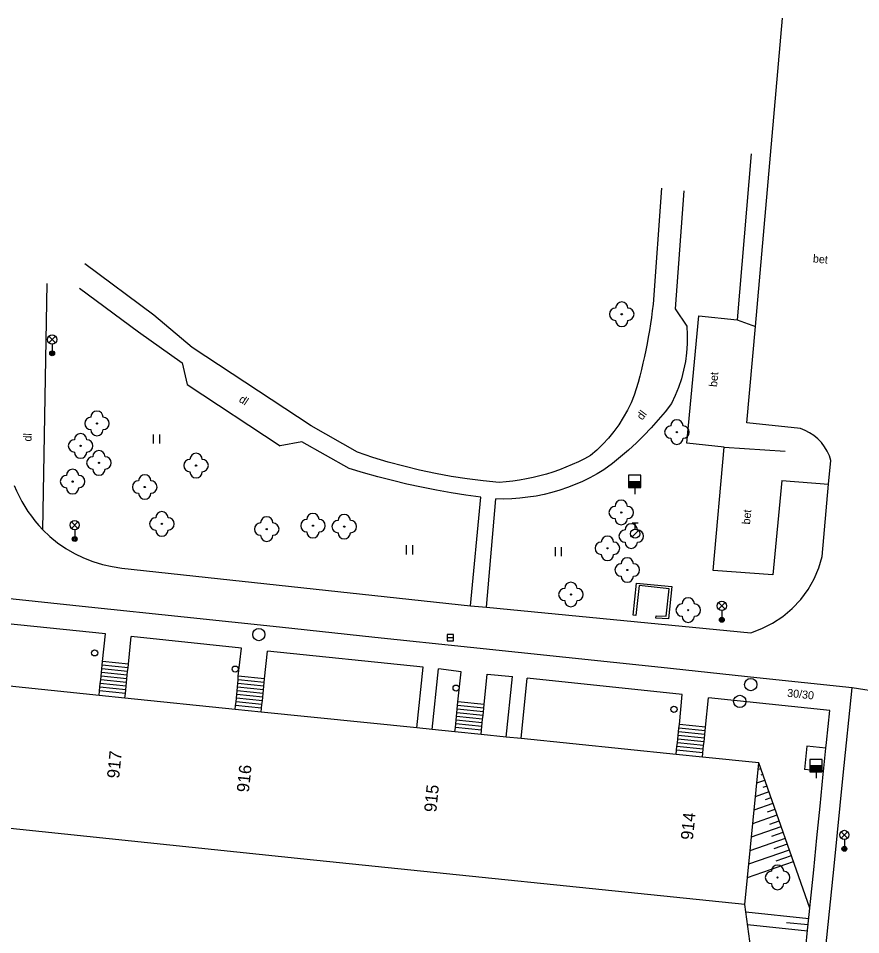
# Model space of a CAD drawing. Extents: x -539244 to -537359, y -1183785 to -1181851.
# Drawn here: x -537476 to -537407.5, y -1181941.5 to -1181867.1 of the extents above; entities that cross this region are included whole.
import ezdxf

# ---------------------------------------------------------------- set-up
doc = ezdxf.new("R2010")
doc.units = 0
for name, color, linetype in [('Vrstva 10', 7, 'Continuous'), ('Vrstva 11', 7, 'Continuous'), ('Vrstva 14', 7, 'Continuous'), ('Vrstva 15', 7, 'Continuous'), ('Vrstva 22', 7, 'Continuous'), ('Vrstva 27', 7, 'Continuous'), ('Vrstva 28', 7, 'Continuous'), ('Vrstva 33', 7, 'Continuous'), ('Vrstva 36', 7, 'Continuous'), ('Vrstva 40', 7, 'Continuous'), ('Vrstva 47', 7, 'Continuous'), ('Vrstva 5', 7, 'Continuous'), ('Vrstva 7', 7, 'Continuous')]:
    doc.layers.add(name, color=color, linetype=linetype)

msp = doc.modelspace()

# ---------------------------------------------------------------- linework, layer by layer
at = {"layer": 'Vrstva 10'}
for p, q in [((-537416.07, -1181892.07), (-537413.86, -1181867.05)), ((-537416.77, -1181899.9), (-537416.07, -1181892.07)), ((-537412.41, -1181900.37), (-537416.77, -1181899.9)), ((-537410.13, -1181904.89), (-537409.93, -1181902.95)), ((-537410.64, -1181910.76), (-537410.13, -1181904.89)), ((-537467.56, -1181911.69), (-537439.23, -1181914.75)), ((-537470.253, -1181914.859), (-537478.01, -1181914.046)), ((-537462.497, -1181915.68), (-537470.253, -1181914.859)), ((-537439.23, -1181914.75), (-537437.91, -1181914.88)), ((-537437.91, -1181914.88), (-537416.44, -1181916.94)), ((-537454.74, -1181916.504), (-537462.497, -1181915.68)), ((-537446.984, -1181917.327), (-537454.74, -1181916.504)), ((-537439.228, -1181918.145), (-537446.984, -1181917.327)), ((-537431.471, -1181918.961), (-537439.228, -1181918.145)), ((-537423.714, -1181919.777), (-537431.471, -1181918.961)), ((-537415.957, -1181920.594), (-537423.714, -1181919.777)), ((-537408.2, -1181921.41), (-537415.957, -1181920.594)), ((-537405.03, -1181921.94), (-537408.2, -1181921.41))]:
    msp.add_line(p, q, dxfattribs=at)
for points in [[(-537409.93, -1181902.95), (-537410.059, -1181902.569), (-537410.231, -1181902.196), (-537410.447, -1181901.838), (-537410.703, -1181901.504), (-537410.996, -1181901.2), (-537411.32, -1181900.93), (-537411.668, -1181900.701), (-537412.034, -1181900.514), (-537412.41, -1181900.37)], [(-537476.3, -1181904.98), (-537476.113, -1181905.419), (-537475.907, -1181905.851), (-537475.682, -1181906.275), (-537475.439, -1181906.689), (-537475.179, -1181907.093), (-537474.901, -1181907.485), (-537474.608, -1181907.865), (-537474.3, -1181908.231), (-537473.977, -1181908.582)], [(-537473.977, -1181908.582), (-537473.398, -1181909.13), (-537472.773, -1181909.637), (-537472.106, -1181910.099), (-537471.403, -1181910.51), (-537470.668, -1181910.865), (-537469.91, -1181911.163), (-537469.134, -1181911.4), (-537468.349, -1181911.576), (-537467.56, -1181911.69)], [(-537416.44, -1181916.94), (-537415.545, -1181916.61), (-537414.672, -1181916.171), (-537413.842, -1181915.624), (-537413.074, -1181914.978), (-537412.384, -1181914.244), (-537411.788, -1181913.436), (-537411.296, -1181912.573), (-537410.913, -1181911.674), (-537410.64, -1181910.76)]]:
    msp.add_lwpolyline(points, dxfattribs=at)
at = {"layer": 'Vrstva 11'}
for p, q in [((-537423.69, -1181880.83), (-537424.39, -1181890.27)), ((-537421.89, -1181881.07), (-537422.6, -1181890.64)), ((-537464.95, -1181891.16), (-537470.57, -1181886.99)), ((-537473.977, -1181908.582), (-537473.63, -1181888.58)), ((-537470.99, -1181888.97), (-537466.21, -1181892.51)), ((-537461.829, -1181893.782), (-537464.95, -1181891.16)), ((-537422.6, -1181890.64), (-537421.64, -1181892.05)), ((-537417.54, -1181891.54), (-537416.07, -1181892.07)), ((-537466.21, -1181892.51), (-537462.65, -1181895.03)), ((-537452.172, -1181900.135), (-537461.829, -1181893.782)), ((-537462.65, -1181895.03), (-537462.25, -1181896.78)), ((-537462.25, -1181896.78), (-537454.68, -1181901.76)), ((-537448.4, -1181902.29), (-537452.172, -1181900.135)), ((-537452.915, -1181901.435), (-537454.68, -1181901.76)), ((-537449.09, -1181903.62), (-537452.915, -1181901.435)), ((-537447.923, -1181903.964), (-537449.09, -1181903.62)), ((-537413.93, -1181904.59), (-537410.13, -1181904.89)), ((-537439.23, -1181914.75), (-537438.39, -1181905.94)), ((-537437.91, -1181914.88), (-537437.17, -1181906.08)), ((-537467.018, -1181919.495), (-537466.79, -1181917.26)), ((-537457.83, -1181918.21), (-537466.79, -1181917.26)), ((-537455.95, -1181920.688), (-537455.72, -1181918.43)), ((-537443.07, -1181919.73), (-537455.72, -1181918.43)), ((-537467.018, -1181919.495), (-537469.13, -1181919.28)), ((-537467.109, -1181920.39), (-537469.21, -1181920.176)), ((-537467.078, -1181920.091), (-537469.179, -1181919.877)), ((-537467.048, -1181919.793), (-537469.149, -1181919.579)), ((-537443.574, -1181924.674), (-537443.07, -1181919.73)), ((-537442.323, -1181924.802), (-537441.82, -1181919.87)), ((-537439.99, -1181920.11), (-537441.82, -1181919.87)), ((-537440.239, -1181922.545), (-537439.99, -1181920.11)), ((-537467.169, -1181920.987), (-537469.27, -1181920.773)), ((-537467.139, -1181920.688), (-537469.24, -1181920.474)), ((-537455.98, -1181920.986), (-537458.091, -1181920.771)), ((-537455.95, -1181920.688), (-537458.09, -1181920.47)), ((-537438.111, -1181922.762), (-537437.86, -1181920.3)), ((-537437.86, -1181920.3), (-537435.82, -1181920.51)), ((-537436.32, -1181925.414), (-537435.82, -1181920.51)), ((-537435.11, -1181925.538), (-537434.61, -1181920.64)), ((-537422.01, -1181921.96), (-537434.61, -1181920.64)), ((-537467.261, -1181921.882), (-537469.362, -1181921.668)), ((-537467.23, -1181921.584), (-537469.331, -1181921.37)), ((-537467.2, -1181921.285), (-537469.301, -1181921.071)), ((-537456.071, -1181921.881), (-537458.182, -1181921.666)), ((-537456.041, -1181921.583), (-537458.152, -1181921.368)), ((-537456.01, -1181921.284), (-537458.121, -1181921.069)), ((-537408.925, -1181928.521), (-537408.2, -1181921.41)), ((-537456.132, -1181922.478), (-537458.243, -1181922.263)), ((-537456.102, -1181922.18), (-537458.213, -1181921.965)), ((-537420.124, -1181924.615), (-537419.88, -1181922.22)), ((-537410.03, -1181923.26), (-537419.88, -1181922.22)), ((-537456.193, -1181923.075), (-537458.304, -1181922.86)), ((-537456.163, -1181922.777), (-537458.274, -1181922.562)), ((-537438.172, -1181923.358), (-537440.299, -1181923.141)), ((-537438.141, -1181923.06), (-537440.269, -1181922.843)), ((-537438.111, -1181922.762), (-537440.239, -1181922.545)), ((-537438.233, -1181923.955), (-537440.36, -1181923.738)), ((-537438.202, -1181923.657), (-537440.33, -1181923.44)), ((-537438.324, -1181924.851), (-537440.452, -1181924.634)), ((-537438.294, -1181924.552), (-537440.421, -1181924.335)), ((-537438.263, -1181924.254), (-537440.391, -1181924.037)), ((-537420.154, -1181924.913), (-537422.289, -1181924.695)), ((-537420.124, -1181924.615), (-537422.23, -1181924.4)), ((-537420.215, -1181925.51), (-537422.35, -1181925.292)), ((-537420.185, -1181925.211), (-537422.319, -1181924.993)), ((-537420.307, -1181926.405), (-537422.441, -1181926.187)), ((-537420.276, -1181926.107), (-537422.411, -1181925.889)), ((-537420.246, -1181925.808), (-537422.38, -1181925.59)), ((-537411.9, -1181926.16), (-537412.09, -1181928.05)), ((-537410.338, -1181926.317), (-537411.9, -1181926.16)), ((-537420.337, -1181926.704), (-537422.472, -1181926.486)), ((-537410.529, -1181928.207), (-537412.09, -1181928.05)), ((-537409.65, -1181935.632), (-537408.925, -1181928.521)), ((-537410.375, -1181942.743), (-537409.65, -1181935.632))]:
    msp.add_line(p, q, dxfattribs=at)
for points in [[(-537424.39, -1181890.27), (-537424.452, -1181890.805), (-537424.521, -1181891.339), (-537424.597, -1181891.872), (-537424.681, -1181892.405), (-537424.772, -1181892.937), (-537424.87, -1181893.467), (-537424.975, -1181893.996), (-537425.088, -1181894.524), (-537425.207, -1181895.05), (-537425.334, -1181895.574), (-537425.467, -1181896.096), (-537425.608, -1181896.616), (-537425.756, -1181897.134), (-537425.91, -1181897.65)], [(-537421.64, -1181892.05), (-537421.603, -1181892.763), (-537421.609, -1181893.482), (-537421.661, -1181894.203), (-537421.758, -1181894.921), (-537421.899, -1181895.633), (-537422.085, -1181896.333), (-537422.313, -1181897.019), (-537422.582, -1181897.685), (-537422.89, -1181898.33)], [(-537425.91, -1181897.65), (-537426.172, -1181898.272), (-537426.471, -1181898.882), (-537426.806, -1181899.476), (-537427.175, -1181900.051), (-537427.577, -1181900.605), (-537428.01, -1181901.134), (-537428.472, -1181901.636), (-537428.959, -1181902.108), (-537429.47, -1181902.55)], [(-537422.89, -1181898.33), (-537423.414, -1181899.007), (-537423.961, -1181899.667), (-537424.532, -1181900.309), (-537425.124, -1181900.931), (-537425.738, -1181901.534), (-537426.371, -1181902.115), (-537427.024, -1181902.673), (-537427.694, -1181903.209), (-537428.38, -1181903.72)], [(-537445.902, -1181903.083), (-537447.157, -1181902.704), (-537448.4, -1181902.29)], [(-537436.88, -1181904.74), (-537438.183, -1181904.612), (-537439.484, -1181904.448), (-537440.782, -1181904.247), (-537442.074, -1181904.009), (-537443.359, -1181903.736), (-537444.635, -1181903.427), (-537445.902, -1181903.083)], [(-537429.47, -1181902.55), (-537429.956, -1181902.813), (-537430.453, -1181903.06), (-537430.958, -1181903.293), (-537431.471, -1181903.51), (-537431.991, -1181903.71), (-537432.519, -1181903.894), (-537433.052, -1181904.061), (-537433.59, -1181904.211), (-537434.133, -1181904.343), (-537434.679, -1181904.458), (-537435.228, -1181904.555), (-537435.778, -1181904.634), (-537436.329, -1181904.696), (-537436.88, -1181904.74)], [(-537428.38, -1181903.72), (-537428.94, -1181904.053), (-537429.517, -1181904.365), (-537430.109, -1181904.653), (-537430.715, -1181904.916), (-537431.333, -1181905.155), (-537431.962, -1181905.367), (-537432.6, -1181905.553), (-537433.245, -1181905.712), (-537433.895, -1181905.843), (-537434.55, -1181905.946), (-537435.206, -1181906.021), (-537435.863, -1181906.068), (-537436.518, -1181906.088), (-537437.17, -1181906.08)], [(-537438.39, -1181905.94), (-537439.595, -1181905.77), (-537440.797, -1181905.578), (-537441.996, -1181905.363), (-537443.192, -1181905.127), (-537444.383, -1181904.869), (-537445.569, -1181904.589), (-537446.749, -1181904.287), (-537447.923, -1181903.964)], [(-537468.89, -1181917.04), (-537478.173, -1181916.08), (-537481.56, -1181915.73)], [(-537469.13, -1181919.28), (-537468.89, -1181917.04)], [(-537458.09, -1181920.47), (-537457.83, -1181918.21)], [(-537469.4, -1181922.039), (-537469.362, -1181921.668), (-537469.331, -1181921.37), (-537469.301, -1181921.071), (-537469.27, -1181920.773), (-537469.24, -1181920.474), (-537469.21, -1181920.176), (-537469.179, -1181919.877), (-537469.149, -1181919.579), (-537469.13, -1181919.28)], [(-537467.299, -1181922.253), (-537467.261, -1181921.882), (-537467.23, -1181921.584), (-537467.2, -1181921.285), (-537467.169, -1181920.987), (-537467.139, -1181920.688), (-537467.109, -1181920.39), (-537467.078, -1181920.091), (-537467.048, -1181919.793), (-537467.018, -1181919.495)], [(-537458.336, -1181923.168), (-537458.304, -1181922.86), (-537458.274, -1181922.562), (-537458.243, -1181922.263), (-537458.213, -1181921.965), (-537458.182, -1181921.666), (-537458.152, -1181921.368), (-537458.121, -1181921.069), (-537458.091, -1181920.771), (-537458.09, -1181920.47)], [(-537456.225, -1181923.383), (-537456.193, -1181923.075), (-537456.163, -1181922.777), (-537456.132, -1181922.478), (-537456.102, -1181922.18), (-537456.071, -1181921.881), (-537456.041, -1181921.583), (-537456.01, -1181921.284), (-537455.98, -1181920.986), (-537455.95, -1181920.688)], [(-537422.23, -1181924.4), (-537422.01, -1181921.96)], [(-537440.488, -1181924.989), (-537440.452, -1181924.634), (-537440.421, -1181924.335), (-537440.391, -1181924.037), (-537440.36, -1181923.738), (-537440.33, -1181923.44), (-537440.299, -1181923.141), (-537440.269, -1181922.843), (-537440.239, -1181922.545)], [(-537438.361, -1181925.206), (-537438.324, -1181924.851), (-537438.294, -1181924.552), (-537438.263, -1181924.254), (-537438.233, -1181923.955), (-537438.202, -1181923.657), (-537438.172, -1181923.358), (-537438.141, -1181923.06), (-537438.111, -1181922.762)], [(-537411.073, -1181933.609), (-537410.812, -1181931.022), (-537410.551, -1181928.434), (-537410.529, -1181928.207), (-537410.338, -1181926.317), (-537410.291, -1181925.847), (-537410.03, -1181923.26)], [(-537422.506, -1181926.824), (-537422.472, -1181926.486), (-537422.441, -1181926.187), (-537422.411, -1181925.889), (-537422.38, -1181925.59), (-537422.35, -1181925.292), (-537422.319, -1181924.993), (-537422.289, -1181924.695), (-537422.23, -1181924.4)], [(-537420.372, -1181927.041), (-537420.337, -1181926.704), (-537420.307, -1181926.405), (-537420.276, -1181926.107), (-537420.246, -1181925.808), (-537420.215, -1181925.51), (-537420.185, -1181925.211), (-537420.154, -1181924.913), (-537420.124, -1181924.615)], [(-537412.114, -1181943.958), (-537411.854, -1181941.371), (-537411.64, -1181939.32), (-537411.594, -1181938.783), (-537411.334, -1181936.196), (-537411.073, -1181933.609)]]:
    msp.add_lwpolyline(points, dxfattribs=at)
at = {"layer": 'Vrstva 14'}
for p, q in [((-537411.64, -1181939.32), (-537415.78, -1181927.51)), ((-537413.813, -1181960.94), (-537416.94, -1181939.02))]:
    msp.add_line(p, q, dxfattribs=at)
at = {"layer": 'Vrstva 15'}
for p, q in [((-537415.833, -1181928.035), (-537415.622, -1181927.961)), ((-537415.608, -1181928.486), (-537415.456, -1181928.433)), ((-537415.944, -1181929.134), (-537415.291, -1181928.905)), ((-537416.054, -1181930.232), (-537414.96, -1181929.849)), ((-537415.431, -1181929.484), (-537415.126, -1181929.377)), ((-537415.255, -1181930.482), (-537414.795, -1181930.321)), ((-537416.165, -1181931.331), (-537414.629, -1181930.792)), ((-537415.079, -1181931.48), (-537414.464, -1181931.264)), ((-537416.276, -1181932.429), (-537414.299, -1181931.736)), ((-537416.386, -1181933.528), (-537413.968, -1181932.68)), ((-537414.902, -1181932.478), (-537414.133, -1181932.208)), ((-537416.497, -1181934.626), (-537413.637, -1181933.623)), ((-537414.726, -1181933.475), (-537413.802, -1181933.152)), ((-537414.55, -1181934.473), (-537413.472, -1181934.095)), ((-537416.608, -1181935.725), (-537413.306, -1181934.567)), ((-537414.374, -1181935.471), (-537413.141, -1181935.039)), ((-537416.719, -1181936.823), (-537412.975, -1181935.511)), ((-537416.859, -1181939.613), (-537411.731, -1181940.152)), ((-537416.705, -1181940.635), (-537411.832, -1181941.147)), ((-537413.531, -1181940.465), (-537411.781, -1181940.649))]:
    msp.add_line(p, q, dxfattribs=at)
at = {"layer": 'Vrstva 22'}
for centre in [(-537426.93, -1181891.08), (-537469.57, -1181899.95), (-537422.45, -1181900.65), (-537470.9, -1181901.77), (-537469.41, -1181903.15), (-537461.52, -1181903.37), (-537471.55, -1181904.67), (-537465.69, -1181905.11), (-537426.97, -1181907.18), (-537464.3, -1181908.11), (-537452.02, -1181908.25), (-537449.48, -1181908.33), (-537455.78, -1181908.53), (-537426.16, -1181909.1), (-537428.09, -1181910.09), (-537426.48, -1181911.85), (-537431.06, -1181913.84), (-537421.53, -1181915.11), (-537414.27, -1181936.82)]:
    msp.add_circle(centre, 0.05, dxfattribs=at)
for centre, start, end in [((-537426.93, -1181890.58), 0, 180), ((-537427.43, -1181891.08), 90, 270), ((-537426.43, -1181891.08), 270, 90), ((-537426.93, -1181891.58), 180, 0), ((-537470.07, -1181899.95), 90, 270), ((-537469.57, -1181899.45), 0, 180), ((-537469.07, -1181899.95), 270, 90), ((-537422.95, -1181900.65), 90, 270), ((-537422.45, -1181900.15), 0, 180), ((-537421.95, -1181900.65), 270, 90), ((-537470.9, -1181901.27), 0, 180), ((-537469.57, -1181900.45), 180, 0), ((-537471.4, -1181901.77), 90, 270), ((-537470.4, -1181901.77), 270, 90), ((-537422.45, -1181901.15), 180, 0), ((-537470.9, -1181902.27), 180, 0), ((-537469.41, -1181902.65), 0, 180), ((-537461.52, -1181902.87), 0, 180), ((-537469.91, -1181903.15), 90, 270), ((-537468.91, -1181903.15), 270, 90), ((-537462.02, -1181903.37), 90, 270), ((-537461.02, -1181903.37), 270, 90), ((-537471.55, -1181904.17), 0, 180), ((-537469.41, -1181903.65), 180, 0), ((-537461.52, -1181903.87), 180, 0), ((-537472.05, -1181904.67), 90, 270), ((-537471.05, -1181904.67), 270, 90), ((-537466.19, -1181905.11), 90, 270), ((-537465.69, -1181904.61), 0, 180), ((-537465.19, -1181905.11), 270, 90), ((-537471.55, -1181905.17), 180, 0), ((-537465.69, -1181905.61), 180, 0), ((-537427.47, -1181907.18), 90, 270), ((-537426.97, -1181906.68), 0, 180), ((-537426.47, -1181907.18), 270, 90), ((-537464.8, -1181908.11), 90, 270), ((-537464.3, -1181907.61), 0, 180), ((-537463.8, -1181908.11), 270, 90), ((-537455.78, -1181908.03), 0, 180), ((-537452.02, -1181907.75), 0, 180), ((-537449.48, -1181907.83), 0, 180), ((-537456.28, -1181908.53), 90, 270), ((-537455.28, -1181908.53), 270, 90), ((-537452.52, -1181908.25), 90, 270), ((-537451.52, -1181908.25), 270, 90), ((-537449.98, -1181908.33), 90, 270), ((-537448.98, -1181908.33), 270, 90), ((-537426.97, -1181907.68), 180, 0), ((-537426.16, -1181908.6), 0, 180), ((-537464.3, -1181908.61), 180, 0), ((-537455.78, -1181909.03), 180, 0), ((-537452.02, -1181908.75), 180, 0), ((-537449.48, -1181908.83), 180, 0), ((-537428.09, -1181909.59), 0, 180), ((-537426.66, -1181909.1), 90, 270), ((-537425.66, -1181909.1), 270, 90), ((-537428.59, -1181910.09), 90, 270), ((-537427.59, -1181910.09), 270, 90), ((-537426.16, -1181909.6), 180, 0), ((-537428.09, -1181910.59), 180, 0), ((-537426.98, -1181911.85), 90, 270), ((-537426.48, -1181911.35), 0, 180), ((-537425.98, -1181911.85), 270, 90), ((-537431.06, -1181913.34), 0, 180), ((-537426.48, -1181912.35), 180, 0), ((-537431.56, -1181913.84), 90, 270), ((-537430.56, -1181913.84), 270, 90), ((-537431.06, -1181914.34), 180, 0), ((-537421.53, -1181914.61), 0, 180), ((-537422.03, -1181915.11), 90, 270), ((-537421.03, -1181915.11), 270, 90), ((-537421.53, -1181915.61), 180, 0), ((-537414.27, -1181936.32), 0, 180), ((-537414.77, -1181936.82), 90, 270), ((-537413.77, -1181936.82), 270, 90), ((-537414.27, -1181937.32), 180, 0)]:
    msp.add_arc(centre, 0.5, start, end, dxfattribs=at)
at = {"layer": 'Vrstva 27'}
msp.add_line((-537441.11, -1181917.34), (-537440.61, -1181917.34), dxfattribs=at)
msp.add_lwpolyline([(-537441.11, -1181917.59), (-537440.61, -1181917.59), (-537440.61, -1181917.09), (-537441.11, -1181917.09)], close=True, dxfattribs=at)
for centre in [(-537456.42, -1181917.09), (-537416.45, -1181921.16), (-537417.34, -1181922.52)]:
    msp.add_circle(centre, 0.5, dxfattribs=at)
at = {"layer": 'Vrstva 28'}
for p, q in [((-537426.38, -1181904.65), (-537425.38, -1181904.65)), ((-537426.38, -1181904.7), (-537425.38, -1181904.7)), ((-537426.38, -1181904.75), (-537425.38, -1181904.75)), ((-537426.38, -1181904.8), (-537425.38, -1181904.8)), ((-537426.38, -1181904.85), (-537425.38, -1181904.85)), ((-537426.38, -1181904.9), (-537425.38, -1181904.9)), ((-537426.38, -1181904.95), (-537425.38, -1181904.95)), ((-537426.38, -1181905), (-537425.38, -1181905)), ((-537426.38, -1181905.05), (-537425.38, -1181905.05)), ((-537426.38, -1181905.1), (-537425.38, -1181905.1)), ((-537425.88, -1181905.15), (-537425.88, -1181905.68)), ((-537426.09, -1181908.025), (-537425.59, -1181908.025)), ((-537425.84, -1181908.525), (-537425.84, -1181908.025)), ((-537426.098, -1181909.172), (-537425.568, -1181908.642)), ((-537411.64, -1181927.73), (-537410.64, -1181927.73)), ((-537411.64, -1181927.78), (-537410.64, -1181927.78)), ((-537411.64, -1181927.83), (-537410.64, -1181927.83)), ((-537411.64, -1181927.88), (-537410.64, -1181927.88)), ((-537411.64, -1181927.93), (-537410.64, -1181927.93)), ((-537411.64, -1181927.98), (-537410.64, -1181927.98)), ((-537411.64, -1181928.03), (-537410.64, -1181928.03)), ((-537411.64, -1181928.08), (-537410.64, -1181928.08)), ((-537411.64, -1181928.13), (-537410.64, -1181928.13)), ((-537411.64, -1181928.18), (-537410.64, -1181928.18)), ((-537411.14, -1181928.23), (-537411.14, -1181928.76))]:
    msp.add_line(p, q, dxfattribs=at)
for points in [[(-537426.38, -1181905.15), (-537425.38, -1181905.15), (-537425.38, -1181904.15), (-537426.38, -1181904.15)], [(-537411.64, -1181928.23), (-537410.64, -1181928.23), (-537410.64, -1181927.23), (-537411.64, -1181927.23)]]:
    msp.add_lwpolyline(points, close=True, dxfattribs=at)
for centre, radius in [((-537425.84, -1181908.9), 0.375), ((-537469.76, -1181918.58), 0.25), ((-537458.34, -1181919.9), 0.25), ((-537440.39, -1181921.44), 0.25), ((-537422.69, -1181923.17), 0.25)]:
    msp.add_circle(centre, radius, dxfattribs=at)
at = {"layer": 'Vrstva 33'}
for p, q in [((-537473.475, -1181893.4), (-537472.945, -1181892.87)), ((-537473.475, -1181892.87), (-537472.945, -1181893.4)), ((-537473.21, -1181893.51), (-537473.21, -1181894.26)), ((-537471.645, -1181908.47), (-537471.115, -1181907.94)), ((-537471.645, -1181907.94), (-537471.115, -1181908.47)), ((-537471.38, -1181908.58), (-537471.38, -1181909.33)), ((-537419.065, -1181915.03), (-537418.535, -1181914.5)), ((-537419.065, -1181914.5), (-537418.535, -1181915.03)), ((-537418.8, -1181915.14), (-537418.8, -1181915.89)), ((-537409.105, -1181933.63), (-537408.575, -1181933.1)), ((-537409.105, -1181933.1), (-537408.575, -1181933.63)), ((-537408.84, -1181933.74), (-537408.84, -1181934.49))]:
    msp.add_line(p, q, dxfattribs=at)
for centre, radius in [((-537473.21, -1181893.135), 0.375), ((-537473.21, -1181894.26), 0.2), ((-537473.21, -1181894.26), 0.145), ((-537473.21, -1181894.26), 0.0876), ((-537471.38, -1181908.205), 0.375), ((-537471.38, -1181909.33), 0.2), ((-537471.38, -1181909.33), 0.145), ((-537471.38, -1181909.33), 0.0876), ((-537418.8, -1181914.765), 0.375), ((-537418.8, -1181915.89), 0.2), ((-537418.8, -1181915.89), 0.145), ((-537418.8, -1181915.89), 0.0876), ((-537408.84, -1181933.365), 0.375), ((-537408.84, -1181934.49), 0.2), ((-537408.84, -1181934.49), 0.145), ((-537408.84, -1181934.49), 0.0876)]:
    msp.add_circle(centre, radius, dxfattribs=at)
at = {"layer": 'Vrstva 36'}
for p, q in [((-537464.972, -1181901.585), (-537464.972, -1181900.835)), ((-537464.472, -1181901.585), (-537464.472, -1181900.835)), ((-537444.41, -1181910.591), (-537444.41, -1181909.841)), ((-537443.91, -1181910.591), (-537443.91, -1181909.841)), ((-537432.32, -1181910.737), (-537432.32, -1181909.987)), ((-537431.82, -1181910.737), (-537431.82, -1181909.987))]:
    msp.add_line(p, q, dxfattribs=at)
at = {"layer": 'Vrstva 5'}
for q in [(-537415.78, -1181927.51), (-537452.77, -1181935.34)]:
    msp.add_line((-537416.94, -1181939.02), q, dxfattribs=at)
for points in [[(-537415.78, -1181927.51), (-537420.372, -1181927.041), (-537422.506, -1181926.824), (-537435.11, -1181925.538), (-537436.32, -1181925.414), (-537438.361, -1181925.206), (-537440.488, -1181924.989), (-537442.323, -1181924.802), (-537443.574, -1181924.674), (-537456.225, -1181923.383), (-537458.336, -1181923.168), (-537467.299, -1181922.253), (-537469.4, -1181922.039), (-537478.01, -1181921.16)], [(-537452.77, -1181935.34), (-537479.492, -1181932.55), (-537503.195, -1181930.076)]]:
    msp.add_lwpolyline(points, dxfattribs=at)
at = {"layer": 'Vrstva 7'}
for p, q in [((-537416.42, -1181878.05), (-537417.54, -1181891.54)), ((-537421.65, -1181901.54), (-537420.67, -1181891.2)), ((-537420.67, -1181891.2), (-537417.54, -1181891.54)), ((-537418.61, -1181901.87), (-537421.65, -1181901.54)), ((-537419.49, -1181911.89), (-537418.61, -1181901.87)), ((-537418.61, -1181901.87), (-537413.66, -1181902.19)), ((-537413.93, -1181904.59), (-537414.64, -1181912.23)), ((-537414.64, -1181912.23), (-537419.49, -1181911.89))]:
    msp.add_line(p, q, dxfattribs=at)
for points in [[(-537425.991, -1181915.518), (-537425.73, -1181912.91), (-537422.847, -1181913.196), (-537423.129, -1181915.815), (-537424.149, -1181915.774)], [(-537424.149, -1181915.774), (-537424.141, -1181915.574), (-537423.308, -1181915.608), (-537423.067, -1181913.373), (-537425.517, -1181913.108), (-537425.792, -1181915.541), (-537425.991, -1181915.518)]]:
    msp.add_lwpolyline(points, dxfattribs=at)

# ---------------------------------------------------------------- texts
at = {"layer": 'Vrstva 40'}
for s, rotation, p in [('bet', 354.47246, (-537411.419, -1181886.863)), ('bet', 84.58582, (-537419.188, -1181897.008)), ('dl', 326.66068, (-537458.093, -1181898.14)), ('dl', 53.23321, (-537425.262, -1181899.728)), ('dl', 88.86775, (-537474.896, -1181901.42)), ('bet', 84.58582, (-537416.508, -1181908.176)), ('30/30', 353.97283, (-537413.511, -1181922.14))]:
    msp.add_text(s, height=0.65, rotation=rotation, dxfattribs=at).set_placement(p)
at = {"layer": 'Vrstva 47'}
for s, p in [(' 917', (-537467.809, -1181929.179)), (' 916', (-537457.265, -1181930.311)), (' 915', (-537442.041, -1181931.923)), (' 914', (-537421.189, -1181934.18))]:
    msp.add_text(s, height=1, rotation=84.17366, dxfattribs=at).set_placement(p)

doc.saveas('drawing.dxf')
